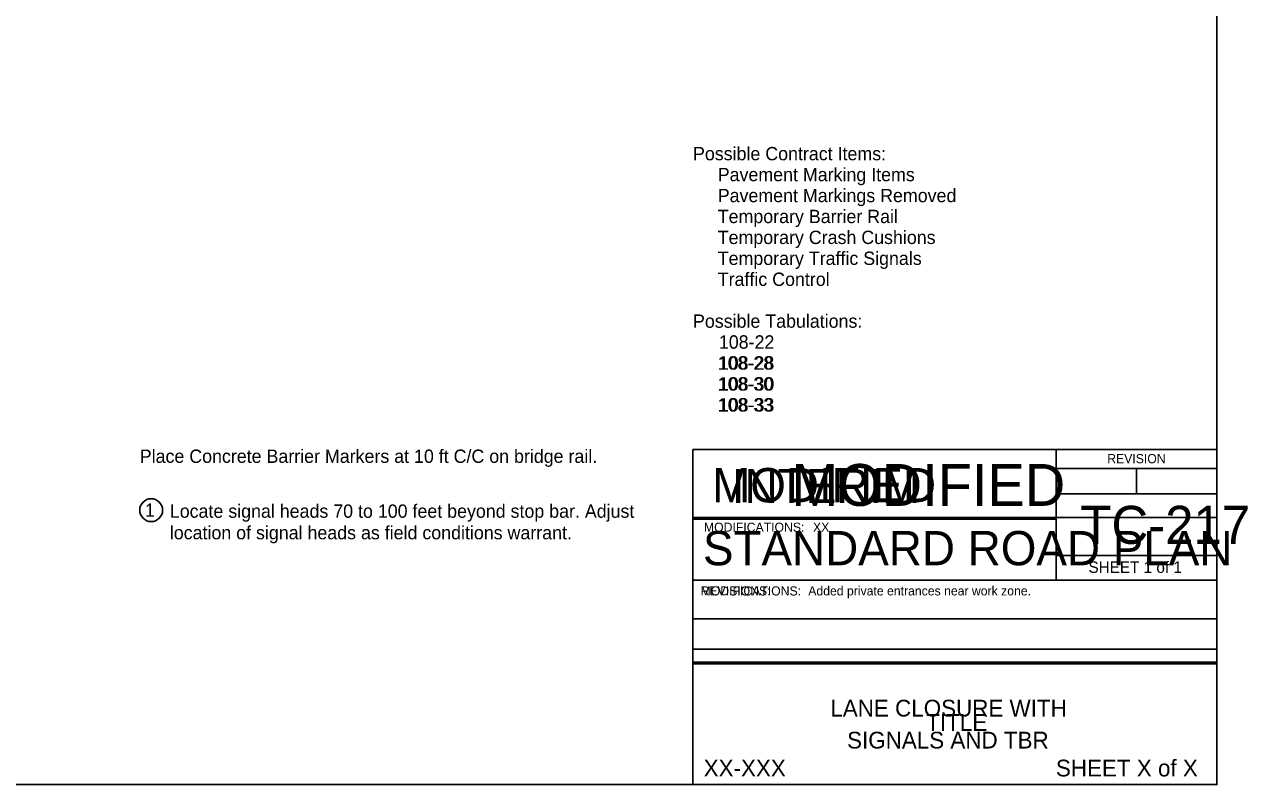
# Model space of a CAD drawing. Extents: x -2134934 to -2127057, y -2139046 to -2137036.
# Drawn here: x -2133366 to -2131759, y -2139046 to -2138047 of the extents above; entities that cross this region are included whole.
import ezdxf

# ---------------------------------------------------------------- set-up
doc = ezdxf.new("R2010")
doc.units = 0
for name, color, linetype in [('BridgeSuperStructureExisting', 7, 'Continuous'), ('Default', 7, 'Continuous'), ('Dimension', 7, 'Continuous'), ('dsnAlignmentCurveData', 7, 'Continuous'), ('dsnAlignmentTic', 7, 'Continuous'), ('dsnCellElements', 7, 'Continuous'), ('DsnShtOutsideBorder', 7, 'Continuous'), ('hwyPlanSheetShape', 7, 'Continuous')]:
    doc.layers.add(name, color=color, linetype=linetype)

msp = doc.modelspace()

# ---------------------------------------------------------------- linework, layer by layer
at = {"layer": 'BridgeSuperStructureExisting'}
msp.add_circle((-2133199.2, -2138685.5), 15, dxfattribs=at)
at = {"layer": 'Default'}
msp.add_lwpolyline([(-2134934.4, -2137035.9), (-2131799.4, -2137035.9), (-2131799.4, -2139045.9), (-2134934.4, -2139045.9)], close=True, dxfattribs=at)
at = {"layer": 'Dimension'}
for p, q in [((-2132010.4, -2138605.9), (-2132010.4, -2138697.3)), ((-2132010.4, -2138630.9), (-2131799.4, -2138630.9)), ((-2131904.9, -2138630.9), (-2131904.9, -2138664.1)), ((-2132010.4, -2138664.1), (-2131799.4, -2138664.1)), ((-2132487.5, -2138697.3), (-2132010.4, -2138697.3)), ((-2132010.4, -2138697.3), (-2132010.4, -2138777.3)), ((-2131799.4, -2138745.1), (-2132010.4, -2138745.1)), ((-2132487.5, -2138777.3), (-2131799.4, -2138777.3)), ((-2132487.5, -2138828.3), (-2131799.4, -2138828.3)), ((-2132487.5, -2138868.3), (-2131799.4, -2138868.3)), ((-2132487.5, -2138887.3), (-2131799.4, -2138887.3))]:
    msp.add_line(p, q, dxfattribs=at)
msp.add_lwpolyline([(-2132487.5, -2138605.9), (-2131799.4, -2138605.9), (-2131799.4, -2139045.9), (-2132487.5, -2139045.9)], close=True, dxfattribs=at)
at = {"layer": 'DsnShtOutsideBorder'}
for p, q in [((-2132487.5, -2138695), (-2131799.4, -2138695)), ((-2132487.5, -2138885), (-2131799.4, -2138885))]:
    msp.add_line(p, q, dxfattribs=at)
msp.add_lwpolyline([(-2132487.5, -2138605.9), (-2131799.4, -2138605.9), (-2131799.4, -2139045.9), (-2132487.5, -2139045.9)], close=True, dxfattribs=at)

# ---------------------------------------------------------------- texts
at = {"layer": 'BridgeSuperStructureExisting'}
for s, p in [('1', (-2133207.3, -2138694.2)), ('Locate signal heads 70 to 100 feet beyond stop bar. Adjust ', (-2133174.7, -2138695.5)), ('location of signal heads as field conditions warrant.', (-2133174.7, -2138723.8))]:
    msp.add_text(s, height=17.5, dxfattribs=at).set_placement(p)
at = {"layer": 'Dimension'}
for s, height, p in [('REVISION', 12, (-2131943.4, -2138623.8)), ('TC-217', 50, (-2131978.7, -2138729.8)), ('STANDARD ROAD PLAN', 45.001, (-2132474.4, -2138757.9)), ('SHEET 1 of 1', 15, (-2131968, -2138767.9)), ('Added private entrances near work zone.', 12, (-2132336.1, -2138797.5)), ('LANE CLOSURE WITH', 22, (-2132307.1, -2138956.6)), ('SIGNALS AND TBR', 22, (-2132285.1, -2138998.6))]:
    msp.add_text(s, height=height, dxfattribs=at).set_placement(p)
at = {"layer": 'dsnAlignmentCurveData'}
msp.add_text('REVISIONS:', height=12, dxfattribs=at).set_placement((-2132477.5, -2138797.6))
at = {"layer": 'dsnAlignmentTic'}
for s, height, p in [('MODIFIED', 45, (-2132462.4, -2138675.1)), ('MODIFICATIONS:', 12, (-2132477.5, -2138797.6))]:
    msp.add_text(s, height=height, dxfattribs=at).set_placement(p)
at = {"layer": 'dsnCellElements'}
for s, p in [('Possible Contract Items:', (-2132487.5, -2138225.9)), ('     Pavement Marking Items', (-2132487.5, -2138253.4)), ('     Pavement Markings Removed', (-2132487.5, -2138280.9)), ('     Temporary Barrier Rail', (-2132487.5, -2138308.4)), ('     Temporary Crash Cushions', (-2132487.5, -2138335.9)), ('     Temporary Traffic Signals', (-2132487.5, -2138363.4)), ('     Traffic Control', (-2132487.5, -2138390.9)), ('Possible Tabulations:', (-2132487.5, -2138445.9)), ('108-22', (-2132453.5, -2138473.3)), ('108-22', (-2132453.5, -2138473.4)), ('     108-28', (-2132487.5, -2138500.9)), ('108-28', (-2132453.5, -2138500.9)), ('     108-30', (-2132487.5, -2138528.4)), ('108-30', (-2132453.5, -2138528.4)), ('     108-33', (-2132487.5, -2138555.9)), ('108-33', (-2132453.5, -2138555.9)), ('Place Concrete Barrier Markers at 10 ft C/C on bridge rail.', (-2133214.2, -2138623.4))]:
    msp.add_text(s, height=17.5, dxfattribs=at).set_placement(p)
at = {"layer": 'DsnShtOutsideBorder'}
for s, height, p in [('MODIFIED', 55, (-2132358.1, -2138679.9)), ('MODIFICATIONS:', 12, (-2132473.1, -2138713.9)), ('XX', 12, (-2132329.9, -2138713.9)), ('TITLE', 22, (-2132181.1, -2138975.4)), ('XX-XXX', 22, (-2132473.5, -2139035.3)), ('SHEET X of X', 22, (-2132010.8, -2139035.3))]:
    msp.add_text(s, height=height, dxfattribs=at).set_placement(p)
at = {"layer": 'hwyPlanSheetShape'}
msp.add_text('INTERIM', height=45, dxfattribs=at).set_placement((-2132436.5, -2138676.3))

doc.saveas('drawing.dxf')
